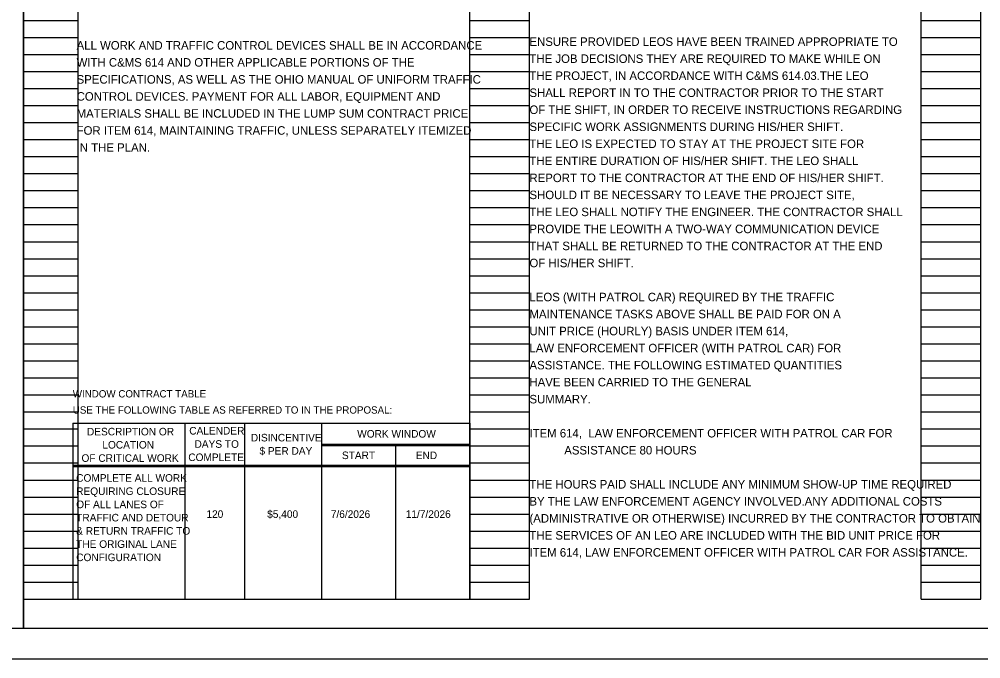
# Model space of a CAD drawing. Extents: x -10.6 to 44.1, y -11.1 to 22.
# Drawn here: x 1.43 to 17.24, y 0 to 10.52 of the extents above; entities that cross this region are included whole.
import ezdxf

# ---------------------------------------------------------------- set-up
doc = ezdxf.new("R2010")
doc.units = 0
for name, color, linetype in [('SH_Border', 7, 'Continuous'), ('SH_Cut_Line', 7, 'Continuous'), ('SH_Data', 7, 'Continuous'), ('SH_Text', 7, 'Continuous')]:
    doc.layers.add(name, color=color, linetype=linetype)

msp = doc.modelspace()

# ---------------------------------------------------------------- linework, layer by layer
at = {"layer": 'SH_Border'}
for points in [[(0.5, 21.5), (1.5, 21.5), (1.5, 0.5), (0.5, 0.5)], [(1.5, 21.5), (33.5, 21.5), (33.5, 0.5), (1.5, 0.5)]]:
    msp.add_lwpolyline(points, close=True, dxfattribs=at)
at = {"layer": 'SH_Cut_Line'}
msp.add_lwpolyline([(0, 0), (34, 0), (34, 22), (0, 22)], close=True, dxfattribs=at)
at = {"layer": 'SH_Data'}
for p, q in [((1.5, 0.98), (1.5, 21.14)), ((2.4, 0.98), (2.4, 21.14)), ((8.84, 0.98), (8.84, 21.14)), ((9.82, 0.98), (9.82, 21.14)), ((16.26, 0.98), (16.26, 21.14)), ((17.24, 0.98), (17.24, 21.14)), ((1.5, 10.5), (2.4, 10.5)), ((8.84, 10.5), (9.82, 10.5)), ((16.26, 10.5), (17.24, 10.5)), ((1.5, 10.22), (2.4, 10.22)), ((8.84, 10.22), (9.82, 10.22)), ((16.26, 10.22), (17.24, 10.22)), ((1.5, 9.94), (2.4, 9.94)), ((8.84, 9.94), (9.82, 9.94)), ((16.26, 9.94), (17.24, 9.94)), ((1.5, 9.66), (2.4, 9.66)), ((8.84, 9.66), (9.82, 9.66)), ((16.26, 9.66), (17.24, 9.66)), ((1.5, 9.38), (2.4, 9.38)), ((8.84, 9.38), (9.82, 9.38)), ((16.26, 9.38), (17.24, 9.38)), ((1.5, 9.1), (2.4, 9.1)), ((8.84, 9.1), (9.82, 9.1)), ((16.26, 9.1), (17.24, 9.1)), ((1.5, 8.82), (2.4, 8.82)), ((8.84, 8.82), (9.82, 8.82)), ((16.26, 8.82), (17.24, 8.82)), ((1.5, 8.54), (2.4, 8.54)), ((8.84, 8.54), (9.82, 8.54)), ((16.26, 8.54), (17.24, 8.54)), ((1.5, 8.26), (2.4, 8.26)), ((8.84, 8.26), (9.82, 8.26)), ((16.26, 8.26), (17.24, 8.26)), ((1.5, 7.98), (2.4, 7.98)), ((8.84, 7.98), (9.82, 7.98)), ((16.26, 7.98), (17.24, 7.98)), ((1.5, 7.7), (2.4, 7.7)), ((8.84, 7.7), (9.82, 7.7)), ((16.26, 7.7), (17.24, 7.7)), ((1.5, 7.42), (2.4, 7.42)), ((8.84, 7.42), (9.82, 7.42)), ((16.26, 7.42), (17.24, 7.42)), ((1.5, 7.14), (2.4, 7.14)), ((8.84, 7.14), (9.82, 7.14)), ((16.26, 7.14), (17.24, 7.14)), ((1.5, 6.86), (2.4, 6.86)), ((8.84, 6.86), (9.82, 6.86)), ((16.26, 6.86), (17.24, 6.86)), ((1.5, 6.58), (2.4, 6.58)), ((8.84, 6.58), (9.82, 6.58)), ((16.26, 6.58), (17.24, 6.58)), ((1.5, 6.3), (2.4, 6.3)), ((8.84, 6.3), (9.82, 6.3)), ((16.26, 6.3), (17.24, 6.3)), ((1.5, 6.02), (2.4, 6.02)), ((8.84, 6.02), (9.82, 6.02)), ((16.26, 6.02), (17.24, 6.02)), ((1.5, 5.74), (2.4, 5.74)), ((8.84, 5.74), (9.82, 5.74)), ((16.26, 5.74), (17.24, 5.74)), ((1.5, 5.46), (2.4, 5.46)), ((8.84, 5.46), (9.82, 5.46)), ((16.26, 5.46), (17.24, 5.46)), ((1.5, 5.18), (2.4, 5.18)), ((8.84, 5.18), (9.82, 5.18)), ((16.26, 5.18), (17.24, 5.18)), ((1.5, 4.9), (2.4, 4.9)), ((8.84, 4.9), (9.82, 4.9)), ((16.26, 4.9), (17.24, 4.9)), ((1.5, 4.62), (2.4, 4.62)), ((8.84, 4.62), (9.82, 4.62)), ((16.26, 4.62), (17.24, 4.62)), ((1.5, 4.34), (2.4, 4.34)), ((8.84, 4.34), (9.82, 4.34)), ((16.26, 4.34), (17.24, 4.34)), ((1.5, 4.06), (2.4, 4.06)), ((8.84, 4.06), (9.82, 4.06)), ((16.26, 4.06), (17.24, 4.06)), ((2.312, 3.873), (8.84, 3.873)), ((2.312, 3.873), (2.312, 3.165)), ((4.156, 3.873), (4.156, 3.07)), ((5.137, 3.873), (5.137, 3.07)), ((6.4, 3.873), (6.4, 3.07)), ((8.84, 3.873), (8.84, 3.052)), ((1.5, 3.78), (2.4, 3.78)), ((8.84, 3.78), (9.82, 3.78)), ((16.26, 3.78), (17.24, 3.78)), ((1.5, 3.5), (2.4, 3.5)), ((6.4, 3.528), (8.84, 3.528)), ((6.4, 3.51), (8.84, 3.51)), ((7.62, 3.51), (7.62, 3.165)), ((8.84, 3.5), (9.82, 3.5)), ((16.26, 3.5), (17.24, 3.5)), ((1.5, 3.22), (2.4, 3.22)), ((2.312, 3.183), (8.84, 3.183)), ((2.312, 3.165), (8.84, 3.165)), ((2.312, 3.165), (8.84, 3.165)), ((2.312, 3.165), (2.312, 0.98)), ((4.156, 3.165), (4.156, 0.98)), ((5.137, 3.165), (5.137, 0.98)), ((6.4, 3.165), (6.4, 0.98)), ((7.62, 3.165), (7.62, 0.98)), ((8.84, 3.22), (9.82, 3.22)), ((8.84, 3.183), (8.84, 3.165)), ((8.84, 3.165), (8.84, 0.98)), ((16.26, 3.22), (17.24, 3.22)), ((1.5, 2.94), (2.4, 2.94)), ((8.84, 2.94), (9.82, 2.94)), ((16.26, 2.94), (17.24, 2.94)), ((1.5, 2.66), (2.4, 2.66)), ((8.84, 2.66), (9.82, 2.66)), ((16.26, 2.66), (17.24, 2.66)), ((1.5, 2.38), (2.4, 2.38)), ((8.84, 2.38), (9.82, 2.38)), ((16.26, 2.38), (17.24, 2.38)), ((1.5, 2.1), (2.4, 2.1)), ((8.84, 2.1), (9.82, 2.1)), ((16.26, 2.1), (17.24, 2.1)), ((1.5, 1.82), (2.4, 1.82)), ((8.84, 1.82), (9.82, 1.82)), ((16.26, 1.82), (17.24, 1.82)), ((1.5, 1.54), (2.4, 1.54)), ((8.84, 1.54), (9.82, 1.54)), ((16.26, 1.54), (17.24, 1.54)), ((1.5, 1.26), (2.4, 1.26)), ((8.84, 1.26), (9.82, 1.26)), ((16.26, 1.26), (17.24, 1.26)), ((1.5, 0.98), (2.4, 0.98)), ((2.312, 0.98), (8.84, 0.98)), ((8.84, 0.98), (9.82, 0.98)), ((16.26, 0.98), (17.24, 0.98))]:
    msp.add_line(p, q, dxfattribs=at)

# ---------------------------------------------------------------- texts
at = {"layer": 'SH_Text'}
for s, height, p in [('ALL WORK AND TRAFFIC CONTROL DEVICES SHALL BE IN ACCORDANCE ', 0.14, (2.375, 10.019)), ('ENSURE PROVIDED LEOS HAVE BEEN TRAINED APPROPRIATE TO', 0.14, (9.82, 10.08)), ('WITH C&MS 614 AND OTHER APPLICABLE PORTIONS OF THE ', 0.14, (2.375, 9.739)), ('THE JOB DECISIONS THEY ARE REQUIRED TO MAKE WHILE ON', 0.14, (9.82, 9.8)), ('THE PROJECT, IN ACCORDANCE WITH C&MS 614.03.THE LEO', 0.14, (9.82, 9.52)), ('SPECIFICATIONS, AS WELL AS THE OHIO MANUAL OF UNIFORM TRAFFIC ', 0.14, (2.375, 9.459)), ('SHALL REPORT IN TO THE CONTRACTOR PRIOR TO THE START', 0.14, (9.82, 9.24)), ('CONTROL DEVICES. PAYMENT FOR ALL LABOR, EQUIPMENT AND ', 0.14, (2.375, 9.179)), ('MATERIALS SHALL BE INCLUDED IN THE LUMP SUM CONTRACT PRICE ', 0.14, (2.375, 8.899)), ('OF THE SHIFT, IN ORDER TO RECEIVE INSTRUCTIONS REGARDING', 0.14, (9.82, 8.96)), ('FOR ITEM 614, MAINTAINING TRAFFIC, UNLESS SEPARATELY ITEMIZED ', 0.14, (2.375, 8.619)), ('SPECIFIC WORK ASSIGNMENTS DURING HIS/HER SHIFT.', 0.14, (9.82, 8.68)), ('THE LEO IS EXPECTED TO STAY AT THE PROJECT SITE FOR', 0.14, (9.82, 8.4)), ('IN THE PLAN.', 0.14, (2.375, 8.339)), ('THE ENTIRE DURATION OF HIS/HER SHIFT. THE LEO SHALL', 0.14, (9.82, 8.12)), ('REPORT TO THE CONTRACTOR AT THE END OF HIS/HER SHIFT.', 0.14, (9.82, 7.84)), ('SHOULD IT BE NECESSARY TO LEAVE THE PROJECT SITE,', 0.14, (9.82, 7.56)), ('THE LEO SHALL NOTIFY THE ENGINEER. THE CONTRACTOR SHALL', 0.14, (9.82, 7.28)), ('PROVIDE THE LEOWITH A TWO-WAY COMMUNICATION DEVICE', 0.14, (9.82, 7)), ('THAT SHALL BE RETURNED TO THE CONTRACTOR AT THE END', 0.14, (9.82, 6.72)), ('OF HIS/HER SHIFT.', 0.14, (9.82, 6.44)), ('LEOS (WITH PATROL CAR) REQUIRED BY THE TRAFFIC', 0.14, (9.82, 5.88)), ('MAINTENANCE TASKS ABOVE SHALL BE PAID FOR ON A', 0.14, (9.82, 5.6)), ('UNIT PRICE (HOURLY) BASIS UNDER ITEM 614,', 0.14, (9.82, 5.32)), ('LAW ENFORCEMENT OFFICER (WITH PATROL CAR) FOR', 0.14, (9.82, 5.04)), ('ASSISTANCE. THE FOLLOWING ESTIMATED QUANTITIES', 0.14, (9.82, 4.76)), ('HAVE BEEN CARRIED TO THE GENERAL', 0.14, (9.82, 4.48)), ('WINDOW CONTRACT TABLE', 0.12, (2.312, 4.298)), ('SUMMARY.', 0.14, (9.82, 4.2)), ('USE THE FOLLOWING TABLE AS REFERRED TO IN THE PROPOSAL:', 0.12, (2.312, 4.032)), ('DESCRIPTION OR ', 0.12435, (2.545, 3.674)), ('CALENDER ', 0.1244, (4.227, 3.688)), ('DISINCENTIVE ', 0.12435, (5.239, 3.575)), ('WORK WINDOW', 0.12435, (6.988, 3.638)), ('ITEM 614,  LAW ENFORCEMENT OFFICER WITH PATROL CAR FOR', 0.14, (9.82, 3.64)), ('LOCATION', 0.1244, (2.798, 3.457)), ('DAYS TO ', 0.1244, (4.313, 3.47)), ('$ PER DAY', 0.1244, (5.381, 3.357)), ('           ASSISTANCE 80 HOURS', 0.14, (9.82, 3.36)), ('OF CRITICAL WORK', 0.12435, (2.455, 3.239)), ('COMPLETE', 0.1244, (4.211, 3.252)), ('START', 0.1244, (6.737, 3.284)), ('END', 0.1244, (7.951, 3.284)), ('COMPLETE ALL WORK ', 0.12435, (2.368, 2.912)), ('THE HOURS PAID SHALL INCLUDE ANY MINIMUM SHOW-UP TIME REQUIRED', 0.14, (9.82, 2.8)), ('REQUIRING CLOSURE ', 0.12435, (2.368, 2.694)), ('OF ALL LANES OF ', 0.12435, (2.368, 2.477)), ('BY THE LAW ENFORCEMENT AGENCY INVOLVED.ANY ADDITIONAL COSTS', 0.14, (9.82, 2.52)), ('TRAFFIC AND DETOUR ', 0.12435, (2.368, 2.259)), ('120', 0.1244, (4.509, 2.317)), ('$5,400', 0.1244, (5.508, 2.317)), ('7/6/2026', 0.1244, (6.554, 2.317)), ('11/7/2026', 0.1244, (7.786, 2.317)), ('(ADMINISTRATIVE OR OTHERWISE) INCURRED BY THE CONTRACTOR TO OBTAIN', 0.14, (9.82, 2.24)), ('& RETURN TRAFFIC TO ', 0.12435, (2.368, 2.041)), ('THE SERVICES OF AN LEO ARE INCLUDED WITH THE BID UNIT PRICE FOR', 0.14, (9.82, 1.96)), ('THE ORIGINAL LANE ', 0.12435, (2.368, 1.824)), ('ITEM 614, LAW ENFORCEMENT OFFICER WITH PATROL CAR FOR ASSISTANCE.', 0.14, (9.82, 1.68)), ('CONFIGURATION ', 0.12435, (2.368, 1.606))]:
    msp.add_text(s, height=height, dxfattribs=at).set_placement(p)

doc.saveas('drawing.dxf')
